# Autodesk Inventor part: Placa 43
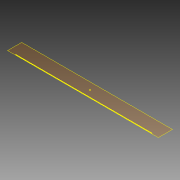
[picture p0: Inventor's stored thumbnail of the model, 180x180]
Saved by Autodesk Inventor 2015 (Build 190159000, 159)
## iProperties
Created: 2015-04
Part Number: Placa 43
Material: Generic
Document SubType Name: Modeling
Designer: suporte
Density: 1 g/cm^3
Appearance: Default
Author: suporte
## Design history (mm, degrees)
workplane "Work Plane1"
sketch "Sketch1"
  geometry: L1 (800, -75)-(-185, -75) reference; 1 further point
  constraints: 1 other
  node "Reference1"
